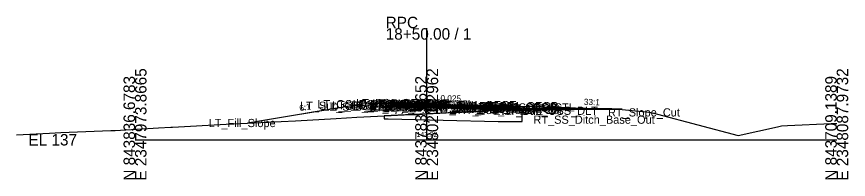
# Model space of a CAD drawing. Extents: x -26 to 203, y -10 to 7538.
# Drawn here: x 0 to 202.8, y 4990.3 to 5030.1 of the extents above; entities that cross this region are included whole.
import ezdxf

# ---------------------------------------------------------------- set-up
doc = ezdxf.new("R2010")
doc.units = 0
for name, color, linetype in [('Default', 7, 'Continuous'), ('Exist Cross Section Cell', 7, 'Continuous'), ('Exist XS Center Line Elevation Label', 7, 'Continuous'), ('Exist XS Ground Line', 7, 'Continuous'), ('Prop CMT Pvmt Course 1', 7, 'Continuous'), ('Prop CMT Pvmt Course 2', 7, 'Continuous'), ('Prop CMT Pvmt Course 3', 7, 'Continuous'), ('Prop CMT Pvmt Surface', 7, 'Continuous'), ('Prop CMT Pvmt Surface Shoulder', 7, 'Continuous'), ('Prop CMT Shld Paved Course 1', 7, 'Continuous'), ('Prop CMT Shld Paved Course 2', 7, 'Continuous'), ('Prop CMT Shld Paved Course 3', 7, 'Continuous'), ('Prop CMT Slope Grass', 7, 'Continuous'), ('Prop CMT Subgrade Earthwork', 7, 'Continuous'), ('Prop Road Sect_ Recs - UC (Outline)', 7, 'Continuous'), ('Prop XS Earthwork Shape', 7, 'Continuous'), ('Prop XS SE Text', 7, 'Continuous'), ('Prop XS Side Slope Text', 7, 'Continuous'), ('Scratch_Level_0', 7, 'Continuous')]:
    doc.layers.add(name, color=color, linetype=linetype)

msp = doc.modelspace()

# ---------------------------------------------------------------- linework, layer by layer
at = {"layer": 'Exist Cross Section Cell'}
for p, q in [((100, 5000), (100, 5027.29)), ((28.87, 5000), (100, 5000)), ((100, 5000), (200, 5000))]:
    msp.add_line(p, q, dxfattribs=at)
at = {"layer": 'Exist XS Ground Line'}
msp.add_lwpolyline([(0, 5001.21), (8, 5001.63), (10.8, 5001.75), (23, 5002.25), (24.04, 5002.3), (34.61, 5002.92), (37.64, 5003.1), (38, 5003.12), (51.06, 5003.83), (53, 5003.93), (64.48, 5004.5), (67.99, 5004.67), (77.9, 5005.19), (82.99, 5005.49), (91.31, 5005.92), (94.47, 5006.07), (97.99, 5006.21), (100, 5006.32), (104.73, 5006.56), (108.63, 5006.79), (117.59, 5007.29), (123.28, 5007.6), (124.42, 5007.66), (124.79, 5007.67), (126.73, 5007.75), (127.53, 5007.75), (128.61, 5007.75), (130.8, 5007.74), (132.34, 5007.74), (133.32, 5007.73), (134.18, 5007.72), (135.09, 5007.71), (136.12, 5007.7), (136.88, 5007.69), (137.56, 5007.68), (138.64, 5007.67), (139.87, 5007.65), (140.89, 5007.63), (142.32, 5007.61), (143.18, 5007.59), (143.54, 5007.59), (144.21, 5007.57), (145.17, 5007.54), (145.53, 5007.52), (146.85, 5007.46), (154.19, 5006.74), (154.69, 5006.69), (156.33, 5006.23), (175.94, 5001.02), (185.53, 5003.19), (186.54, 5003.39), (187.98, 5003.48), (198.66, 5003.98), (200, 5003.99)], dxfattribs=at)
at = {"layer": 'Prop CMT Pvmt Course 1'}
for p, q in [((100, 5008.79), (96, 5008.89)), ((96, 5008.89), (96, 5008.64)), ((96, 5008.64), (100, 5008.54)), ((100, 5008.54), (100, 5008.79)), ((100, 5008.79), (112, 5008.49)), ((100, 5008.54), (100, 5008.79)), ((100, 5008.54), (100, 5008.67)), ((100, 5008.67), (100, 5008.67)), ((100, 5008.67), (100, 5008.54)), ((100, 5008.54), (100, 5008.67)), ((100, 5008.67), (100, 5008.67)), ((100, 5008.67), (100, 5008.54)), ((100, 5008.54), (100, 5008.54)), ((112, 5008.24), (100, 5008.54)), ((100, 5008.54), (100, 5008.54)), ((112, 5008.49), (112, 5008.24))]:
    msp.add_line(p, q, dxfattribs=at)
at = {"layer": 'Prop CMT Pvmt Course 2'}
for p, q in [((100, 5008.54), (96, 5008.64)), ((96, 5008.64), (96, 5008.31)), ((96, 5008.31), (100, 5008.21)), ((100, 5008.21), (100, 5008.54)), ((100, 5008.21), (100, 5008.54)), ((100, 5008.54), (112, 5008.24)), ((112, 5007.91), (100, 5008.21)), ((112, 5008.24), (112, 5007.91))]:
    msp.add_line(p, q, dxfattribs=at)
at = {"layer": 'Prop CMT Pvmt Course 3'}
for p, q in [((100, 5008.21), (96, 5008.31)), ((96, 5008.31), (96, 5007.98)), ((100, 5007.88), (100, 5008.21)), ((100, 5008.21), (112, 5007.91)), ((100, 5007.88), (100, 5008.21)), ((96, 5007.98), (100, 5007.88)), ((112, 5007.58), (100, 5007.88)), ((112, 5007.91), (112, 5007.58))]:
    msp.add_line(p, q, dxfattribs=at)
at = {"layer": 'Prop CMT Pvmt Surface'}
for q in [(96, 5008.89), (112, 5008.49)]:
    msp.add_line((100, 5008.79), q, dxfattribs=at)
at = {"layer": 'Prop CMT Pvmt Surface Shoulder'}
for p, q in [((96, 5008.89), (92, 5008.99)), ((112, 5008.49), (122, 5008.24))]:
    msp.add_line(p, q, dxfattribs=at)
at = {"layer": 'Prop CMT Shld Paved Course 1'}
for p, q in [((92, 5008.99), (91.76, 5008.75)), ((91.76, 5008.75), (96, 5008.64)), ((96, 5008.89), (92, 5008.99)), ((96, 5008.64), (96, 5008.89)), ((112, 5008.49), (122, 5008.24)), ((112, 5008.24), (112, 5008.49)), ((122.26, 5007.99), (112, 5008.24)), ((122, 5008.24), (122.26, 5007.99))]:
    msp.add_line(p, q, dxfattribs=at)
at = {"layer": 'Prop CMT Shld Paved Course 2'}
for p, q in [((91.76, 5008.75), (91.43, 5008.42)), ((91.43, 5008.42), (96, 5008.31)), ((96, 5008.64), (91.76, 5008.75)), ((96, 5008.31), (96, 5008.64)), ((112, 5008.24), (122.26, 5007.99)), ((112, 5007.91), (112, 5008.24)), ((122.6, 5007.64), (112, 5007.91)), ((122.26, 5007.99), (122.6, 5007.64))]:
    msp.add_line(p, q, dxfattribs=at)
at = {"layer": 'Prop CMT Shld Paved Course 3'}
for p, q in [((90.93, 5008.44), (90.61, 5008.11)), ((91.43, 5008.42), (90.93, 5008.44)), ((96, 5008.31), (91.43, 5008.42)), ((96, 5007.98), (96, 5008.31)), ((90.61, 5008.11), (96, 5007.98)), ((112, 5007.91), (122.6, 5007.64)), ((112, 5007.58), (112, 5007.91)), ((123.44, 5007.29), (112, 5007.58)), ((122.6, 5007.64), (123.1, 5007.63)), ((123.1, 5007.63), (123.44, 5007.29))]:
    msp.add_line(p, q, dxfattribs=at)
at = {"layer": 'Prop CMT Slope Grass'}
for p, q in [((84, 5008.71), (56.3, 5004.1)), ((92, 5008.99), (84, 5008.71)), ((122, 5008.24), (126, 5008.1)), ((126, 5008.1), (146.72, 5007.47))]:
    msp.add_line(p, q, dxfattribs=at)
at = {"layer": 'Prop CMT Subgrade Earthwork'}
for p, q in [((90.61, 5008.11), (81.72, 5008.33)), ((96, 5007.98), (90.61, 5008.11)), ((100, 5007.88), (96, 5007.98)), ((100, 5007.88), (112, 5007.58)), ((112, 5007.58), (123.44, 5007.29)), ((123.44, 5007.29), (146.72, 5007.47))]:
    msp.add_line(p, q, dxfattribs=at)
at = {"layer": 'Prop Road Sect_ Recs - UC (Outline)'}
msp.add_lwpolyline([(117.44, 5004.44), (123.28, 5004.44), (123.28, 5007.6), (117.59, 5007.29), (108.63, 5006.79), (100, 5006.32), (91.31, 5005.92), (90.63, 5005.89), (89.63, 5005.85), (89.66, 5005.14), (90.61, 5005.11)], close=True, dxfattribs=at)
at = {"layer": 'Prop XS Earthwork Shape'}
for points in [[(96, 5007.98), (90.61, 5008.11), (81.72, 5008.33), (56.3, 5004.1), (64.48, 5004.5), (67.99, 5004.67), (77.9, 5005.19), (82.99, 5005.49), (91.31, 5005.92), (94.47, 5006.07), (97.99, 5006.21), (100, 5006.32), (104.73, 5006.56), (108.63, 5006.79), (117.59, 5007.29), (119.48, 5007.39), (112, 5007.58), (100, 5007.88)], [(142.44, 5007.6), (146.25, 5007.49), (146.6, 5007.47), (123.44, 5007.29), (119.48, 5007.39), (123.28, 5007.6), (124.42, 5007.66), (124.79, 5007.67), (126.73, 5007.75), (127.53, 5007.75), (128.61, 5007.75), (130.8, 5007.74), (132.34, 5007.74), (133.32, 5007.73), (134.18, 5007.72), (135.09, 5007.71), (136.12, 5007.7), (136.88, 5007.69), (137.56, 5007.68), (138.64, 5007.67), (139.87, 5007.65), (140.89, 5007.63), (142.32, 5007.61)], [(142.44, 5007.6), (146.25, 5007.49), (145.53, 5007.52), (145.17, 5007.54), (144.21, 5007.57), (143.54, 5007.59), (143.18, 5007.59)]]:
    msp.add_lwpolyline(points, close=True, dxfattribs=at)

# ---------------------------------------------------------------- texts
at = {"layer": 'Default'}
msp.add_text('-', height=0.0001, dxfattribs=at).set_placement((28.87, 5000))
at = {"layer": 'Exist Cross Section Cell'}
for s, p in [('RPC', (90, 5027.29)), ('18+50.00 / 1', (90, 5024.49)), ('EL 137', (2.87, 4998.6))]:
    msp.add_text(s, height=2.8, dxfattribs=at).set_placement(p)
for s, p in [('E 2347973.8665', (31.67, 4990)), ('E 2348021.2962', (102.8, 4990)), ('E 2348087.9732', (202.8, 4990)), ('N 843836.6783', (28.87, 4990)), ('N 843783.6652', (100, 4990)), ('N 843709.1389', (200, 4990))]:
    msp.add_text(s, height=2.8, rotation=90, dxfattribs=at).set_placement(p)
at = {"layer": 'Exist XS Center Line Elevation Label'}
msp.add_text('143.32', height=1.2, dxfattribs=at).set_placement((97.55, 5000.72))
at = {"layer": 'Prop XS SE Text'}
msp.add_text('0.025', height=1.5, rotation=358.5679, dxfattribs=at).set_placement((103.34, 5009.46))
at = {"layer": 'Prop XS Side Slope Text'}
for s, rotation, p in [('6:1', 9.4623, (69.08, 5006.97)), ('33:1', 358.2643, (138.32, 5008.54))]:
    msp.add_text(s, height=1.5, rotation=rotation, dxfattribs=at).set_placement(p)
at = {"layer": 'Scratch_Level_0'}
for s, p in [('LT_Sub_OSS_DLT', (69.12, 5007.33)), ('LT_GS_OS_CTL', (73.37, 5007.71)), ('LT_Sub_Trench_Out', (74.81, 5007.11)), ('LT_PS3_Shelf_Out', (76.92, 5007.44)), ('LT_PS3_OEOP', (81.67, 5007.42)), ('LT_PS2_OEOP', (81.99, 5007.75)), ('LT_PS1_OEOP', (82.8, 5007.99)), ('LT_Sub_OEOT', (86.08, 5006.98)), ('LT_PV2_OEOT', (86.17, 5007.64)), ('LT_PV3_OEOT', (86.17, 5007.31)), ('LT_PV1_OEOT', (86.74, 5007.89)), ('RT_Sub_OEEOP', (89.17, 5006.88)), ('LT_Sub_OEEOP', (89.21, 5006.88)), ('RT_PV2_OEEOP', (89.26, 5007.54)), ('RT_PV3_OEEOP', (89.26, 5007.21)), ('LT_PV2_OEEOP', (89.31, 5007.54)), ('LT_PV3_OEEOP', (89.31, 5007.21)), ('RT_PV1_OEEOP', (89.83, 5007.67)), ('LT_PV1_OEEOP', (89.87, 5007.67)), ('RT_PV2_IEEOP', (89.91, 5007.54)), ('LT_PV2_IEEOP', (89.95, 5007.54)), ('RT_PV1_IEEOP', (90.47, 5007.67)), ('LT_PV1_IEEOP', (90.52, 5007.67)), ('PV2_PGL', (93.91, 5007.54)), ('PV1_PGL', (94.47, 5007.79)), ('RT_Sub_OEOT', (102.03, 5006.58)), ('RT_PV2_OEOT', (102.13, 5007.24)), ('RT_PV3_OEOT', (102.13, 5006.91)), ('RT_PV1_OEOT', (102.69, 5007.49)), ('RT_Sub_Trench_Out', (107.6, 5006.29)), ('RT_PS3_Shelf_Out', (109.04, 5006.63)), ('RT_PS2_OEOP', (112.45, 5006.99)), ('RT_PS1_OEOP', (112.76, 5007.24)), ('RT_PS3_OEOP', (112.79, 5006.64)), ('RT_GS_OS_CTL', (115.32, 5006.92)), ('RT_Sub_OSS_DLT', (118.27, 5006.1)), ('RT_Slope_Cut', (144.22, 5005.7)), ('LT_Fill_Slope', (46.82, 5003.1)), ('RT_SS_Ditch_Base_Out', (126.03, 5003.92))]:
    msp.add_text(s, height=2, dxfattribs=at).set_placement(p)

doc.saveas('drawing.dxf')
